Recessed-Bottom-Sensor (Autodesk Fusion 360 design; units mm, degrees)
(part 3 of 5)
sketch "Restore cam service opening after obsolete bore closure" plane through (23.9, 0, 0) normal (1, 0, 0) x axis (0, 0, -1)
  line L1 (-42.2047, 46.7373) -> (-43.8497, 47.5044)
  line L2 (-40.5875, 45.9133) -> (-42.2047, 46.7373)
  line L3 (-39, 45.0333) -> (-40.5875, 45.9133)
  line L4 (-37.4442, 44.0985) -> (-39, 45.0333)
  line L5 (-35.922, 43.11) -> (-37.4442, 44.0985)
  line L6 (-34.4352, 42.0689) -> (-35.922, 43.11)
  line L7 (-32.9856, 40.9766) -> (-34.4352, 42.0689)
  line L8 (-31.575, 39.8343) -> (-32.9856, 40.9766)
  line L9 (-30.2052, 38.6435) -> (-31.575, 39.8343)
  line L10 (-28.8778, 37.4057) -> (-30.2052, 38.6435)
  line L11 (-27.5943, 36.1222) -> (-28.8778, 37.4057)
  line L12 (-26.3565, 34.7948) -> (-27.5943, 36.1222)
  line L13 (-25.1657, 33.425) -> (-26.3565, 34.7948)
  line L14 (-24.0234, 32.0144) -> (-25.1657, 33.425)
  line L15 (-22.9311, 30.5648) -> (-24.0234, 32.0144)
  line L16 (-21.89, 29.078) -> (-22.9311, 30.5648)
  line L17 (-20.9015, 27.5558) -> (-21.89, 29.078)
  line L18 (-19.9667, 26) -> (-20.9015, 27.5558)
  line L19 (-19.0867, 24.4125) -> (-19.9667, 26)
  line L20 (-18.2627, 22.7953) -> (-19.0867, 24.4125)
  line L21 (-17.4956, 21.1503) -> (-18.2627, 22.7953)
  line L22 (-16.7864, 19.4795) -> (-17.4956, 21.1503)
  line L23 (-16.136, 17.785) -> (-16.7864, 19.4795)
  line L24 (-15.5451, 16.0689) -> (-16.136, 17.785)
  line L25 (-15.0144, 14.3331) -> (-15.5451, 16.0689)
  line L26 (-14.5446, 12.5799) -> (-15.0144, 14.3331)
  line L27 (-14.1363, 10.8114) -> (-14.5446, 12.5799)
  line L28 (-13.79, 9.0297) -> (-14.1363, 10.8114)
  line L29 (-13.5061, 7.237) -> (-13.79, 9.0297)
  line L30 (-13.2849, 5.4355) -> (-13.5061, 7.237)
  line L31 (-13.1267, 3.6273) -> (-13.2849, 5.4355)
  line L32 (-13.0317, 1.8148) -> (-13.1267, 3.6273)
  line L33 (-13, 0) -> (-13.0317, 1.8148)
  line L34 (-13.0317, -1.8148) -> (-13, 0)
  line L35 (-13.1267, -3.6273) -> (-13.0317, -1.8148)
  line L36 (-13.2849, -5.4355) -> (-13.1267, -3.6273)
  line L37 (-13.5061, -7.237) -> (-13.2849, -5.4355)
  line L38 (-13.79, -9.0297) -> (-13.5061, -7.237)
  line L39 (-14.1363, -10.8114) -> (-13.79, -9.0297)
  line L40 (-14.5446, -12.5799) -> (-14.1363, -10.8114)
  line L41 (-15.0144, -14.3331) -> (-14.5446, -12.5799)
  line L42 (-15.5451, -16.0689) -> (-15.0144, -14.3331)
  line L43 (-16.136, -17.785) -> (-15.5451, -16.0689)
  line L44 (-16.7864, -19.4795) -> (-16.136, -17.785)
  line L45 (-17.4956, -21.1503) -> (-16.7864, -19.4795)
  line L46 (-18.2627, -22.7953) -> (-17.4956, -21.1503)
  line L47 (-19.0867, -24.4125) -> (-18.2627, -22.7953)
  line L48 (-19.9667, -26) -> (-19.0867, -24.4125)
  line L49 (-20.9015, -27.5558) -> (-19.9667, -26)
  line L50 (-21.89, -29.078) -> (-20.9015, -27.5558)
  line L51 (-22.9311, -30.5648) -> (-21.89, -29.078)
  line L52 (-24.0234, -32.0144) -> (-22.9311, -30.5648)
  line L53 (-25.1657, -33.425) -> (-24.0234, -32.0144)
  line L54 (-26.3565, -34.7948) -> (-25.1657, -33.425)
  line L55 (-27.5943, -36.1222) -> (-26.3565, -34.7948)
  line L56 (-28.8778, -37.4057) -> (-27.5943, -36.1222)
  line L57 (-30.2052, -38.6435) -> (-28.8778, -37.4057)
  line L58 (-31.575, -39.8343) -> (-30.2052, -38.6435)
  line L59 (-32.9856, -40.9766) -> (-31.575, -39.8343)
  line L60 (-34.4352, -42.0689) -> (-32.9856, -40.9766)
  line L61 (-35.922, -43.11) -> (-34.4352, -42.0689)
  line L62 (-37.4442, -44.0985) -> (-35.922, -43.11)
  line L63 (-39, -45.0333) -> (-37.4442, -44.0985)
  line L64 (-40.5875, -45.9133) -> (-39, -45.0333)
  line L65 (-42.2047, -46.7373) -> (-40.5875, -45.9133)
  line L66 (-43.8497, -47.5044) -> (-42.2047, -46.7373)
  line L67 (-54.4248, -23.7522) -> (-43.8497, -47.5044)
  line L68 (-53.6024, -23.3686) -> (-54.4248, -23.7522)
  line L69 (-52.7937, -22.9566) -> (-53.6024, -23.3686)
  line L70 (-52, -22.5167) -> (-52.7937, -22.9566)
  line L71 (-51.2221, -22.0493) -> (-52, -22.5167)
  line L72 (-50.461, -21.555) -> (-51.2221, -22.0493)
  line L73 (-49.7176, -21.0344) -> (-50.461, -21.555)
  line L74 (-48.9928, -20.4883) -> (-49.7176, -21.0344)
  line L75 (-48.2875, -19.9172) -> (-48.9928, -20.4883)
  line L76 (-47.6026, -19.3218) -> (-48.2875, -19.9172)
  line L77 (-46.9389, -18.7028) -> (-47.6026, -19.3218)
  line L78 (-46.2972, -18.0611) -> (-46.9389, -18.7028)
  line L79 (-45.6782, -17.3974) -> (-46.2972, -18.0611)
  line L80 (-45.0828, -16.7125) -> (-45.6782, -17.3974)
  line L81 (-44.5117, -16.0072) -> (-45.0828, -16.7125)
  line L82 (-43.9656, -15.2824) -> (-44.5117, -16.0072)
  line L83 (-43.445, -14.539) -> (-43.9656, -15.2824)
  line L84 (-42.9507, -13.7779) -> (-43.445, -14.539)
  line L85 (-42.4833, -13) -> (-42.9507, -13.7779)
  line L86 (-42.0434, -12.2063) -> (-42.4833, -13)
  line L87 (-41.6314, -11.3976) -> (-42.0434, -12.2063)
  line L88 (-41.2478, -10.5752) -> (-41.6314, -11.3976)
  line L89 (-40.8932, -9.7398) -> (-41.2478, -10.5752)
  line L90 (-40.568, -8.8925) -> (-40.8932, -9.7398)
  line L91 (-40.2725, -8.0344) -> (-40.568, -8.8925)
  line L92 (-40.0072, -7.1666) -> (-40.2725, -8.0344)
  line L93 (-39.7723, -6.29) -> (-40.0072, -7.1666)
  line L94 (-39.5682, -5.4057) -> (-39.7723, -6.29)
  line L95 (-39.395, -4.5149) -> (-39.5682, -5.4057)
  line L96 (-39.253, -3.6185) -> (-39.395, -4.5149)
  line L97 (-39.1424, -2.7177) -> (-39.253, -3.6185)
  line L98 (-39.0633, -1.8137) -> (-39.1424, -2.7177)
  line L99 (-39.0158, -0.9074) -> (-39.0633, -1.8137)
  line L100 (-39, 0) -> (-39.0158, -0.9074)
  line L101 (-39.0158, 0.9074) -> (-39, 0)
  line L102 (-39.0633, 1.8137) -> (-39.0158, 0.9074)
  line L103 (-39.1424, 2.7177) -> (-39.0633, 1.8137)
  line L104 (-39.253, 3.6185) -> (-39.1424, 2.7177)
  line L105 (-39.395, 4.5149) -> (-39.253, 3.6185)
  line L106 (-39.5682, 5.4057) -> (-39.395, 4.5149)
  line L107 (-39.7723, 6.29) -> (-39.5682, 5.4057)
  line L108 (-40.0072, 7.1666) -> (-39.7723, 6.29)
  line L109 (-40.2725, 8.0344) -> (-40.0072, 7.1666)
  line L110 (-40.568, 8.8925) -> (-40.2725, 8.0344)
  line L111 (-40.8932, 9.7398) -> (-40.568, 8.8925)
  line L112 (-41.2478, 10.5752) -> (-40.8932, 9.7398)
  line L113 (-41.6314, 11.3976) -> (-41.2478, 10.5752)
  line L114 (-42.0434, 12.2063) -> (-41.6314, 11.3976)
  line L115 (-42.4833, 13) -> (-42.0434, 12.2063)
  line L116 (-42.9507, 13.7779) -> (-42.4833, 13)
  line L117 (-43.445, 14.539) -> (-42.9507, 13.7779)
  line L118 (-43.9656, 15.2824) -> (-43.445, 14.539)
  line L119 (-44.5117, 16.0072) -> (-43.9656, 15.2824)
  line L120 (-45.0828, 16.7125) -> (-44.5117, 16.0072)
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extrude "Extrude47" cut sketch "Restore cam service opening after obsolete bore closure" along normal blind 12.2
work_plane "WorkPlane48" AlongDistance -15.4 ExtraOffset 0
sketch "Fill former M5 stop nut pocket" plane through (-15.4, 0, 0) normal (1, 0, 0) x axis (0, 0, -1)
  circle C1 centre (-79.6754, -33.9652) radius 4.9
extrude "Extrude48" add sketch "Fill former M5 stop nut pocket" along normal blind 6.4
work_plane "WorkPlane49" AlongDistance -36 ExtraOffset 0
sketch "Fill former M5 stop bore" plane through (-36, 0, 0) normal (1, 0, 0) x axis (0, 0, -1)
  circle C1 centre (-79.6754, -33.9652) radius 2.71
extrude "Extrude49" add sketch "Fill former M5 stop bore" along normal blind 27
work_plane "WorkPlane50" AlongDistance -36.1 ExtraOffset 0
sketch "M3 stop reinforcement bore" plane through (-36.1, 0, 0) normal (1, 0, 0) x axis (0, 0, -1)
  circle C1 centre (-79.6754, -33.9652) radius 1.7
extrude "Extrude50" cut sketch "M3 stop reinforcement bore" along normal blind 27.2
work_plane "WorkPlane51" AlongDistance -13.5 ExtraOffset 0
sketch "Captive M3 locknut stop pocket" plane through (-13.5, 0, 0) normal (1, 0, 0) x axis (0, 0, -1)
  line L1 (-82.5754, -32.2908) -> (-79.6754, -30.6165)
  line L2 (-82.5754, -35.6395) -> (-82.5754, -32.2908)
  line L3 (-79.6754, -37.3138) -> (-82.5754, -35.6395)
  line L4 (-76.7754, -35.6395) -> (-79.6754, -37.3138)
  line L5 (-76.7754, -32.2908) -> (-76.7754, -35.6395)
  line L6 (-79.6754, -30.6165) -> (-76.7754, -32.2908)
extrude "Extrude51" cut sketch "Captive M3 locknut stop pocket" along normal blind 4.6
work_plane "WorkPlane52" AlongDistance -15.4 ExtraOffset 0
sketch "Fill former M5 stop nut pocket (1)" plane through (-15.4, 0, 0) normal (1, 0, 0) x axis (0, 0, -1)
  circle C1 centre (-79.6754, 33.9652) radius 4.9
extrude "Extrude52" add sketch "Fill former M5 stop nut pocket (1)" along normal blind 6.4
work_plane "WorkPlane53" AlongDistance -36 ExtraOffset 0
sketch "Fill former M5 stop bore (1)" plane through (-36, 0, 0) normal (1, 0, 0) x axis (0, 0, -1)
  circle C1 centre (-79.6754, 33.9652) radius 2.71
extrude "Extrude53" add sketch "Fill former M5 stop bore (1)" along normal blind 27
work_plane "WorkPlane54" AlongDistance -36.1 ExtraOffset 0
sketch "M3 stop reinforcement bore (1)" plane through (-36.1, 0, 0) normal (1, 0, 0) x axis (0, 0, -1)
  circle C1 centre (-79.6754, 33.9652) radius 1.7
extrude "Extrude54" cut sketch "M3 stop reinforcement bore (1)" along normal blind 27.2
work_plane "WorkPlane55" AlongDistance -13.5 ExtraOffset 0
sketch "Captive M3 locknut stop pocket (1)" plane through (-13.5, 0, 0) normal (1, 0, 0) x axis (0, 0, -1)
  line L1 (-82.5754, 35.6395) -> (-79.6754, 37.3138)
  line L2 (-82.5754, 32.2908) -> (-82.5754, 35.6395)
  line L3 (-79.6754, 30.6165) -> (-82.5754, 32.2908)
  line L4 (-76.7754, 32.2908) -> (-79.6754, 30.6165)
  line L5 (-76.7754, 35.6395) -> (-76.7754, 32.2908)
  line L6 (-79.6754, 37.3138) -> (-76.7754, 35.6395)
extrude "Extrude55" cut sketch "Captive M3 locknut stop pocket (1)" along normal blind 4.6
work_plane "WorkPlane56" AlongDistance -17.5 ExtraOffset 0
sketch "Recess M3 locknut to keep bolt inside stop" plane through (-17.5, 0, 0) normal (1, 0, 0) x axis (0, 0, -1)
  line L1 (-82.5754, -32.2908) -> (-79.6754, -30.6165)
  line L2 (-82.5754, -35.6395) -> (-82.5754, -32.2908)
  line L3 (-79.6754, -37.3138) -> (-82.5754, -35.6395)
  line L4 (-76.7754, -35.6395) -> (-79.6754, -37.3138)
  line L5 (-76.7754, -32.2908) -> (-76.7754, -35.6395)
  line L6 (-79.6754, -30.6165) -> (-76.7754, -32.2908)
extrude "Extrude56" cut sketch "Recess M3 locknut to keep bolt inside stop" along normal blind 4.01
work_plane "WorkPlane57" AlongDistance -17.5 ExtraOffset 0
sketch "Recess M3 locknut to keep bolt inside stop (1)" plane through (-17.5, 0, 0) normal (1, 0, 0) x axis (0, 0, -1)
  line L1 (-82.5754, 35.6395) -> (-79.6754, 37.3138)
  line L2 (-82.5754, 32.2908) -> (-82.5754, 35.6395)
  line L3 (-79.6754, 30.6165) -> (-82.5754, 32.2908)
  line L4 (-76.7754, 32.2908) -> (-79.6754, 30.6165)
  line L5 (-76.7754, 35.6395) -> (-76.7754, 32.2908)
  line L6 (-79.6754, 37.3138) -> (-76.7754, 35.6395)
extrude "Extrude57" cut sketch "Recess M3 locknut to keep bolt inside stop (1)" along normal blind 4.01
work_plane "WorkPlane6" AlongDistance -7.2 ExtraOffset 0
sketch "Upright socket roof 45 degrees" plane through (0, -7.2, 0) normal (0, 1, 0) x axis (1, 0, 0)
  line L1 (-7.2, -196) -> (0, -196)
  line L2 (0, -203.2) -> (-7.2, -196)
  line L3 (0, -196) -> (0, -203.2)
extrude "Extrude5" cut sketch "Upright socket roof 45 degrees" along normal blind 14.4
work_plane "WorkPlane8" AlongDistance -7.2 ExtraOffset 0
sketch "Upright socket roof 45 degrees" plane through (0, -7.2, 0) normal (0, 1, 0) x axis (1, 0, 0)
  line L1 (7.2, -196) -> (0, -196)
  line L2 (0, -203.2) -> (7.2, -196)
  line L3 (0, -196) -> (0, -203.2)
extrude "Extrude7" cut sketch "Upright socket roof 45 degrees" along normal blind 14.4
work_plane "WorkPlane58" AlongDistance -36 ExtraOffset 0
sketch "Stock M5x14 mounting seat Z64" plane through (-36, 0, 0) normal (1, 0, 0) x axis (0, 0, -1)
  line L1 (-63, -70) -> (-63, -95)
  line L2 (-64, -70) -> (-63, -70)
  line L3 (-64, -95) -> (-64, -70)
  line L4 (-63, -95) -> (-64, -95)
extrude "Extrude58" add sketch "Stock M5x14 mounting seat Z64" along normal blind 12
work_plane "WorkPlane59" AlongDistance 62.9 ExtraOffset 0
sketch "Continue rail clearance through new seat" plane through (0, 0, 62.9) normal (0, 0, 1) x axis (1, 0, 0)
  circle C1 centre (-30, -85) radius 2.7
extrude "Extrude59" cut sketch "Continue rail clearance through new seat" along normal blind 1.2
work_plane "WorkPlane60" AlongDistance -36 ExtraOffset 0
sketch "Stock M5x14 mounting seat Z64 (1)" plane through (-36, 0, 0) normal (1, 0, 0) x axis (0, 0, -1)
  line L1 (-63, 95) -> (-63, 70)
  line L2 (-64, 95) -> (-63, 95)
  line L3 (-64, 70) -> (-64, 95)
  line L4 (-63, 70) -> (-64, 70)
extrude "Extrude60" add sketch "Stock M5x14 mounting seat Z64 (1)" along normal blind 12
work_plane "WorkPlane61" AlongDistance 62.9 ExtraOffset 0
sketch "Continue rail clearance through new seat (1)" plane through (0, 0, 62.9) normal (0, 0, 1) x axis (1, 0, 0)
  circle C1 centre (-30, 85) radius 2.7
extrude "Extrude61" cut sketch "Continue rail clearance through new seat (1)" along normal blind 1.2
work_plane "WorkPlane62" AlongDistance -36 ExtraOffset 0
sketch "Close obsolete long pivot screw hole" plane through (-36, 0, 0) normal (1, 0, 0) x axis (0, 0, -1)
  circle C1 centre (-12, -35) radius 1.71
extrude "Extrude62" add sketch "Close obsolete long pivot screw hole" along normal blind 12
work_plane "WorkPlane63" AlongDistance -26 ExtraOffset 0
sketch "Blind captive printed pivot seat" plane through (-26, 0, 0) normal (1, 0, 0) x axis (0, 0, -1)
  circle C1 centre (-12, -35) radius 4.15
extrude "Extrude63" cut sketch "Blind captive printed pivot seat" along normal blind 2.1
work_plane "WorkPlane48" AlongDistance 24 ExtraOffset 0
sketch "Stock M5x14 mounting seat Z64" plane through (24, 0, 0) normal (1, 0, 0) x axis (0, 0, -1)
  line L1 (-63, -70) -> (-63, -95)
  line L2 (-64, -70) -> (-63, -70)
  line L3 (-64, -95) -> (-64, -70)
  line L4 (-63, -95) -> (-64, -95)
extrude "Extrude48" add sketch "Stock M5x14 mounting seat Z64" along normal blind 12
work_plane "WorkPlane49" AlongDistance 62.9 ExtraOffset 0
sketch "Continue rail clearance through new seat" plane through (0, 0, 62.9) normal (0, 0, 1) x axis (1, 0, 0)
  circle C1 centre (30, -85) radius 2.7
extrude "Extrude49" cut sketch "Continue rail clearance through new seat" along normal blind 1.2
work_plane "WorkPlane50" AlongDistance 24 ExtraOffset 0
sketch "Stock M5x14 mounting seat Z64 (1)" plane through (24, 0, 0) normal (1, 0, 0) x axis (0, 0, -1)
  line L1 (-63, 95) -> (-63, 70)
  line L2 (-64, 95) -> (-63, 95)
  line L3 (-64, 70) -> (-64, 95)
  line L4 (-63, 70) -> (-64, 70)
extrude "Extrude50" add sketch "Stock M5x14 mounting seat Z64 (1)" along normal blind 12
work_plane "WorkPlane51" AlongDistance 62.9 ExtraOffset 0
sketch "Continue rail clearance through new seat (1)" plane through (0, 0, 62.9) normal (0, 0, 1) x axis (1, 0, 0)
  circle C1 centre (30, 85) radius 2.7
extrude "Extrude51" cut sketch "Continue rail clearance through new seat (1)" along normal blind 1.2
work_plane "WorkPlane52" AlongDistance 24 ExtraOffset 0
sketch "Close obsolete long pivot screw hole" plane through (24, 0, 0) normal (1, 0, 0) x axis (0, 0, -1)
  circle C1 centre (-12, -35) radius 1.71
extrude "Extrude52" add sketch "Close obsolete long pivot screw hole" along normal blind 12
work_plane "WorkPlane53" AlongDistance 23.9 ExtraOffset 0
sketch "Blind captive printed pivot seat" plane through (23.9, 0, 0) normal (1, 0, 0) x axis (0, 0, -1)
  circle C1 centre (-12, -35) radius 4.15
extrude "Extrude53" cut sketch "Blind captive printed pivot seat" along normal blind 2.1
work_plane "WorkPlane1" AlongDistance -25.85 ExtraOffset 0
sketch "Captured axle 0.3 mm total end clearance" plane through (-25.85, 0, 0) normal (1, 0, 0) x axis (0, 0, -1)
  circle C1 centre (-12, -35) radius 4
extrude "Extrude1" new body sketch "Captured axle 0.3 mm total end clearance" along normal blind 51.7 bodies "P25 Captured printed pivot lower half"
work_plane "WorkPlane2" AlongDistance -26 ExtraOffset 0
sketch "Longitudinal flat print face" plane through (-26, 0, 0) normal (1, 0, 0) x axis (0, 0, -1)
  line L1 (-7, -30) -> (-7, -35)
  line L2 (-17, -30) -> (-7, -30)
  line L3 (-17, -35) -> (-17, -30)
  line L4 (-7, -35) -> (-17, -35)
extrude "Extrude2" cut sketch "Longitudinal flat print face" along normal blind 52
work_plane "WorkPlane1" AlongDistance -25.85 ExtraOffset 0
sketch "Captured axle 0.3 mm total end clearance" plane through (-25.85, 0, 0) normal (1, 0, 0) x axis (0, 0, -1)
  circle C1 centre (-12, -35) radius 4
extrude "Extrude1" new body sketch "Captured axle 0.3 mm total end clearance" along normal blind 51.7 bodies "P26 Captured printed pivot upper half"
work_plane "WorkPlane2" AlongDistance -26 ExtraOffset 0
sketch "Longitudinal flat print face" plane through (-26, 0, 0) normal (1, 0, 0) x axis (0, 0, -1)
  line L1 (-7, -35) -> (-7, -40)
  line L2 (-17, -35) -> (-7, -35)
  line L3 (-17, -40) -> (-17, -35)
  line L4 (-7, -40) -> (-17, -40)
extrude "Extrude2" cut sketch "Longitudinal flat print face" along normal blind 52
work_plane "WorkPlane9" AlongDistance 9 ExtraOffset 0
sketch "Recess for stocked M3x20 grip screw" plane through (9, 0, 0) normal (1, 0, 0) x axis (0, 0, -1)
  circle C1 centre (-180, 0) radius 3.1
extrude "Extrude8" cut sketch "Recess for stocked M3x20 grip screw" along normal blind 3.6
work_plane "WorkPlane1" AlongDistance -11 ExtraOffset 0
sketch "Grip M3x20 cap head 180" plane through (-11, 0, 0) normal (1, 0, 0) x axis (0, 0, -1)
  circle C1 centre (-180, 0) radius 1.5
extrude "Extrude1" new body sketch "Grip M3x20 cap head 180" along normal blind 20 bodies "HARDWARE Grip M3x20 cap head 180"
work_plane "WorkPlane2" AlongDistance 9 ExtraOffset 0
sketch "Button head" plane through (9, 0, 0) normal (1, 0, 0) x axis (0, 0, -1)
  circle C1 centre (-180, 0) radius 2.75
extrude "Extrude2" add sketch "Button head" along normal blind 3
work_plane "WorkPlane10" AlongDistance 9 ExtraOffset 0
sketch "Recess for stocked M3x20 grip screw (1)" plane through (9, 0, 0) normal (1, 0, 0) x axis (0, 0, -1)
  circle C1 centre (-190, 0) radius 3.1
extrude "Extrude9" cut sketch "Recess for stocked M3x20 grip screw (1)" along normal blind 3.6
work_plane "WorkPlane1" AlongDistance -11 ExtraOffset 0
sketch "Grip M3x20 cap head 190" plane through (-11, 0, 0) normal (1, 0, 0) x axis (0, 0, -1)
  circle C1 centre (-190, 0) radius 1.5
extrude "Extrude1" new body sketch "Grip M3x20 cap head 190" along normal blind 20 bodies "HARDWARE Grip M3x20 cap head 190"
work_plane "WorkPlane2" AlongDistance 9 ExtraOffset 0
sketch "Button head" plane through (9, 0, 0) normal (1, 0, 0) x axis (0, 0, -1)
  circle C1 centre (-190, 0) radius 2.75
extrude "Extrude2" add sketch "Button head" along normal blind 3
work_plane "WorkPlane64" AlongDistance -36.1 ExtraOffset 0
sketch "Stock M3x20 stop recessed cap head" plane through (-36.1, 0, 0) normal (1, 0, 0) x axis (0, 0, -1)
  circle C1 centre (-79.6754, -33.9652) radius 3.1
extrude "Extrude64" cut sketch "Stock M3x20 stop recessed cap head" along normal blind 4.6
work_plane "WorkPlane1" AlongDistance -31.5 ExtraOffset 0
sketch "Stop M3x20 cap head -1" plane through (-31.5, 0, 0) normal (1, 0, 0) x axis (0, 0, -1)
  circle C1 centre (-79.6754, -33.9652) radius 1.5
extrude "Extrude1" new body sketch "Stop M3x20 cap head -1" along normal blind 20 bodies "HARDWARE Stop M3x20 cap head -1"
work_plane "WorkPlane2" AlongDistance -34.5 ExtraOffset 0
sketch "Button head" plane through (-34.5, 0, 0) normal (1, 0, 0) x axis (0, 0, -1)
  circle C1 centre (-79.6754, -33.9652) radius 2.75
extrude "Extrude2" add sketch "Button head" along normal blind 3
work_plane "WorkPlane1" AlongDistance -17.5 ExtraOffset 0
sketch "Stop M3 plain captive nut -1" plane through (-17.5, 0, 0) normal (1, 0, 0) x axis (0, 0, -1)
  line L1 (-82.4254, -32.3774) -> (-79.6754, -30.7897)
  line L2 (-82.4254, -35.5529) -> (-82.4254, -32.3774)
  line L3 (-79.6754, -37.1406) -> (-82.4254, -35.5529)
  line L4 (-76.9254, -35.5529) -> (-79.6754, -37.1406)
  line L5 (-76.9254, -32.3774) -> (-76.9254, -35.5529)
  line L6 (-79.6754, -30.7897) -> (-76.9254, -32.3774)
extrude "Extrude1" new body sketch "Stop M3 plain captive nut -1" along normal blind 2.4 bodies "HARDWARE Stop M3 plain captive nut -1"
work_plane "WorkPlane2" AlongDistance -17.6 ExtraOffset 0
sketch "Thread envelope" plane through (-17.6, 0, 0) normal (1, 0, 0) x axis (0, 0, -1)
  circle C1 centre (-79.6754, -33.9652) radius 1.5
extrude "Extrude2" cut sketch "Thread envelope" along normal blind 2.6
work_plane "WorkPlane65" AlongDistance -36.1 ExtraOffset 0
sketch "Stock M3x20 stop recessed cap head (1)" plane through (-36.1, 0, 0) normal (1, 0, 0) x axis (0, 0, -1)
  circle C1 centre (-79.6754, 33.9652) radius 3.1
extrude "Extrude65" cut sketch "Stock M3x20 stop recessed cap head (1)" along normal blind 4.6
work_plane "WorkPlane1" AlongDistance -31.5 ExtraOffset 0
sketch "Stop M3x20 cap head 1" plane through (-31.5, 0, 0) normal (1, 0, 0) x axis (0, 0, -1)
  circle C1 centre (-79.6754, 33.9652) radius 1.5
extrude "Extrude1" new body sketch "Stop M3x20 cap head 1" along normal blind 20 bodies "HARDWARE Stop M3x20 cap head 1"
work_plane "WorkPlane2" AlongDistance -34.5 ExtraOffset 0
sketch "Button head" plane through (-34.5, 0, 0) normal (1, 0, 0) x axis (0, 0, -1)
  circle C1 centre (-79.6754, 33.9652) radius 2.75
extrude "Extrude2" add sketch "Button head" along normal blind 3
work_plane "WorkPlane1" AlongDistance -17.5 ExtraOffset 0
sketch "Stop M3 plain captive nut 1" plane through (-17.5, 0, 0) normal (1, 0, 0) x axis (0, 0, -1)
  line L1 (-82.4254, 35.5529) -> (-79.6754, 37.1406)
  line L2 (-82.4254, 32.3774) -> (-82.4254, 35.5529)
  line L3 (-79.6754, 30.7897) -> (-82.4254, 32.3774)
  line L4 (-76.9254, 32.3774) -> (-79.6754, 30.7897)
  line L5 (-76.9254, 35.5529) -> (-76.9254, 32.3774)
  line L6 (-79.6754, 37.1406) -> (-76.9254, 35.5529)
extrude "Extrude1" new body sketch "Stop M3 plain captive nut 1" along normal blind 2.4 bodies "HARDWARE Stop M3 plain captive nut 1"
work_plane "WorkPlane2" AlongDistance -17.6 ExtraOffset 0
sketch "Thread envelope" plane through (-17.6, 0, 0) normal (1, 0, 0) x axis (0, 0, -1)
  circle C1 centre (-79.6754, 33.9652) radius 1.5
extrude "Extrude2" cut sketch "Thread envelope" along normal blind 2.6
work_plane "WorkPlane10" AlongDistance 7 ExtraOffset 0
sketch "Bearing inner race support pad" plane through (7, 0, 0) normal (1, 0, 0) x axis (0, 0, -1)
  circle C1 centre (-12, 0) radius 2.4
extrude "Extrude10" add sketch "Bearing inner race support pad" along normal blind 1
work_plane "WorkPlane11" AlongDistance 6.9 ExtraOffset 0
sketch "Preserve roller screw clearance" plane through (6.9, 0, 0) normal (1, 0, 0) x axis (0, 0, -1)
  circle C1 centre (-12, 0) radius 1.7
extrude "Extrude11" cut sketch "Preserve roller screw clearance" along normal blind 1.2
work_plane "WorkPlane12" AlongDistance 16 ExtraOffset 0
sketch "Bearing inner race support pad (1)" plane through (16, 0, 0) normal (1, 0, 0) x axis (0, 0, -1)
  circle C1 centre (-12, 0) radius 2.4
extrude "Extrude12" add sketch "Bearing inner race support pad (1)" along normal blind 1
work_plane "WorkPlane13" AlongDistance 15.9 ExtraOffset 0
sketch "Preserve roller screw clearance (1)" plane through (15.9, 0, 0) normal (1, 0, 0) x axis (0, 0, -1)
  circle C1 centre (-12, 0) radius 1.7
extrude "Extrude13" cut sketch "Preserve roller screw clearance (1)" along normal blind 1.2
work_plane "WorkPlane1" AlongDistance 8 ExtraOffset 0
sketch "Stock 623ZZ envelope 3x10x4" plane through (8, 0, 0) normal (1, 0, 0) x axis (0, 0, -1)
  circle C1 centre (-12, 0) radius 5
extrude "Extrude1" new body sketch "Stock 623ZZ envelope 3x10x4" along normal blind 4 bodies "HARDWARE 623ZZ roller bearing at 8"
work_plane "WorkPlane2" AlongDistance 7.9 ExtraOffset 0
sketch "Bearing inner race bore" plane through (7.9, 0, 0) normal (1, 0, 0) x axis (0, 0, -1)
  circle C1 centre (-12, 0) radius 1.5
extrude "Extrude2" cut sketch "Bearing inner race bore" along normal blind 4.2
work_plane "WorkPlane1" AlongDistance 12 ExtraOffset 0
sketch "Stock 623ZZ envelope 3x10x4" plane through (12, 0, 0) normal (1, 0, 0) x axis (0, 0, -1)
  circle C1 centre (-12, 0) radius 5
extrude "Extrude1" new body sketch "Stock 623ZZ envelope 3x10x4" along normal blind 4 bodies "HARDWARE 623ZZ roller bearing at 12"
work_plane "WorkPlane2" AlongDistance 11.9 ExtraOffset 0
sketch "Bearing inner race bore" plane through (11.9, 0, 0) normal (1, 0, 0) x axis (0, 0, -1)
  circle C1 centre (-12, 0) radius 1.5
extrude "Extrude2" cut sketch "Bearing inner race bore" along normal blind 4.2
work_plane "WorkPlane45" AlongDistance 38 ExtraOffset 0
sketch "Close former long guide bore" plane through (0, 0, 38) normal (0, 0, 1) x axis (1, 0, 0)
  circle C1 centre (5, -55) radius 1.71
extrude "Extrude45" add sketch "Close former long guide bore" along normal blind 21
work_plane "WorkPlane46" AlongDistance 38 ExtraOffset 0
sketch "Close former long guide bore (1)" plane through (0, 0, 38) normal (0, 0, 1) x axis (1, 0, 0)
  circle C1 centre (19, -55) radius 1.71
extrude "Extrude46" add sketch "Close former long guide bore (1)" along normal blind 21
work_plane "WorkPlane47" AlongDistance 38 ExtraOffset 0
sketch "Close obsolete M4 nut pocket" plane through (0, 0, 38) normal (0, 0, 1) x axis (1, 0, 0)
  line L1 (14.1362, -51.3) -> (16.2724, -55)
  line L2 (9.8638, -51.3) -> (14.1362, -51.3)
  line L3 (7.7276, -55) -> (9.8638, -51.3)
  line L4 (9.8638, -58.7) -> (7.7276, -55)
  line L5 (14.1362, -58.7) -> (9.8638, -58.7)
  line L6 (16.2724, -55) -> (14.1362, -58.7)
extrude "Extrude47" add sketch "Close obsolete M4 nut pocket" along normal blind 3.5
work_plane "WorkPlane48" AlongDistance 38 ExtraOffset 0
sketch "Close obsolete M4 adjuster passage" plane through (0, 0, 38) normal (0, 0, 1) x axis (1, 0, 0)
  circle C1 centre (12, -55) radius 2.21
extrude "Extrude48" add sketch "Close obsolete M4 adjuster passage" along normal blind 21
work_plane "WorkPlane49" AlongDistance 37.9 ExtraOffset 0
sketch "M3 preload adjuster passage" plane through (0, 0, 37.9) normal (0, 0, 1) x axis (1, 0, 0)
  circle C1 centre (12, -55) radius 1.7
extrude "Extrude49" cut sketch "M3 preload adjuster passage" along normal blind 21.2
work_plane "WorkPlane50" AlongDistance 37.9 ExtraOffset 0
sketch "M3 preload insert from spring side" plane through (0, 0, 37.9) normal (0, 0, 1) x axis (1, 0, 0)
  circle C1 centre (12, -55) radius 2
extrude "Extrude50" cut sketch "M3 preload insert from spring side" along normal blind 6.9
work_plane "WorkPlane51" AlongDistance 55 ExtraOffset 0
sketch "Recessed preload head and limiter access" plane through (0, 0, 55) normal (0, 0, 1) x axis (1, 0, 0)
  circle C1 centre (12, -55) radius 3.4
extrude "Extrude51" cut sketch "Recessed preload head and limiter access" along normal blind 4.1
work_plane "WorkPlane52" AlongDistance 37.9 ExtraOffset 0
sketch "Short guide M3 insert from underside" plane through (0, 0, 37.9) normal (0, 0, 1) x axis (1, 0, 0)
  circle C1 centre (4, -55) radius 2
extrude "Extrude52" cut sketch "Short guide M3 insert from underside" along normal blind 6.9
work_plane "WorkPlane1" AlongDistance 32 ExtraOffset 0
sketch "Short compression sleeve" plane through (0, 0, 32) normal (0, 0, 1) x axis (1, 0, 0)
  circle C1 centre (4, -55) radius 2.5
extrude "Extrude1" new body sketch "Short compression sleeve" along normal blind 6 bodies "P27 Printed guide sleeve 4"
work_plane "WorkPlane2" AlongDistance 31.9 ExtraOffset 0
sketch "Guide screw bore" plane through (0, 0, 31.9) normal (0, 0, 1) x axis (1, 0, 0)
  circle C1 centre (4, -55) radius 1.65
extrude "Extrude2" cut sketch "Guide screw bore" along normal blind 6.2
work_plane "WorkPlane1" AlongDistance 32 ExtraOffset 0
sketch "Cup guide M3x12 4" plane through (0, 0, 32) normal (0, 0, 1) x axis (1, 0, 0)
  circle C1 centre (4, -55) radius 1.5
extrude "Extrude1" new body sketch "Cup guide M3x12 4" along normal blind 12 bodies "HARDWARE Cup guide M3x12 4"
work_plane "WorkPlane2" AlongDistance 29 ExtraOffset 0
sketch "Button head" plane through (0, 0, 29) normal (0, 0, 1) x axis (1, 0, 0)
  circle C1 centre (4, -55) radius 2.75
extrude "Extrude2" add sketch "Button head" along normal blind 3
work_plane "WorkPlane53" AlongDistance 37.9 ExtraOffset 0
sketch "Short guide M3 insert from underside (1)" plane through (0, 0, 37.9) normal (0, 0, 1) x axis (1, 0, 0)
  circle C1 centre (20, -55) radius 2
extrude "Extrude53" cut sketch "Short guide M3 insert from underside (1)" along normal blind 6.9
work_plane "WorkPlane1" AlongDistance 32 ExtraOffset 0
sketch "Short compression sleeve" plane through (0, 0, 32) normal (0, 0, 1) x axis (1, 0, 0)
  circle C1 centre (20, -55) radius 2.5
extrude "Extrude1" new body sketch "Short compression sleeve" along normal blind 6 bodies "P27 Printed guide sleeve 20"
work_plane "WorkPlane2" AlongDistance 31.9 ExtraOffset 0
sketch "Guide screw bore" plane through (0, 0, 31.9) normal (0, 0, 1) x axis (1, 0, 0)
  circle C1 centre (20, -55) radius 1.65
extrude "Extrude2" cut sketch "Guide screw bore" along normal blind 6.2
work_plane "WorkPlane1" AlongDistance 32 ExtraOffset 0
sketch "Cup guide M3x12 20" plane through (0, 0, 32) normal (0, 0, 1) x axis (1, 0, 0)
  circle C1 centre (20, -55) radius 1.5
extrude "Extrude1" new body sketch "Cup guide M3x12 20" along normal blind 12 bodies "HARDWARE Cup guide M3x12 20"
work_plane "WorkPlane2" AlongDistance 29 ExtraOffset 0
sketch "Button head" plane through (0, 0, 29) normal (0, 0, 1) x axis (1, 0, 0)
  circle C1 centre (20, -55) radius 2.75
extrude "Extrude2" add sketch "Button head" along normal blind 3
work_plane "WorkPlane1" AlongDistance 0.2 ExtraOffset 0
sketch "Wide stock spring seat" plane through (0.2, 0, 0) normal (1, 0, 0) x axis (0, 0, -1)
  line L1 (-35, -49) -> (-35, -61)
  line L2 (-37, -49) -> (-35, -49)
  line L3 (-37, -61) -> (-37, -49)
  line L4 (-35, -61) -> (-37, -61)
extrude "Extrude1" new body sketch "Wide stock spring seat" along normal blind 23.6 bodies "P14 Captive spring cup for 9 mm spring"
work_plane "WorkPlane2" AlongDistance 29 ExtraOffset 0
sketch "Provisional 6 mm spring pilot" plane through (0, 0, 29) normal (0, 0, 1) x axis (1, 0, 0)
  circle C1 centre (12, -55) radius 3
extrude "Extrude2" add sketch "Provisional 6 mm spring pilot" along normal blind 6
work_plane "WorkPlane3" AlongDistance 34.9 ExtraOffset 0
sketch "Printed guide running clearance" plane through (0, 0, 34.9) normal (0, 0, 1) x axis (1, 0, 0)
  circle C1 centre (4, -55) radius 2.7
extrude "Extrude3" cut sketch "Printed guide running clearance" along normal blind 2.2
work_plane "WorkPlane4" AlongDistance 34.9 ExtraOffset 0
sketch "Printed guide running clearance (1)" plane through (0, 0, 34.9) normal (0, 0, 1) x axis (1, 0, 0)
  circle C1 centre (20, -55) radius 2.7
extrude "Extrude4" cut sketch "Printed guide running clearance (1)" along normal blind 2.2
work_plane "WorkPlane1" AlongDistance 55 ExtraOffset 0
sketch "Preserve one mm additional compression limit" plane through (0, 0, 55) normal (0, 0, 1) x axis (1, 0, 0)
  circle C1 centre (12, -55) radius 3.2
extrude "Extrude1" new body sketch "Preserve one mm additional compression limit" along normal blind 2 bodies "P15 Recessed preload limit collar 1 mm"
work_plane "WorkPlane2" AlongDistance 54.9 ExtraOffset 0
sketch "M3 adjuster clearance" plane through (0, 0, 54.9) normal (0, 0, 1) x axis (1, 0, 0)
  circle C1 centre (12, -55) radius 1.7
extrude "Extrude2" cut sketch "M3 adjuster clearance" along normal blind 2.2
work_plane "WorkPlane1" AlongDistance 37 ExtraOffset 0
sketch "Preload M3x20 cap head" plane through (0, 0, 37) normal (0, 0, 1) x axis (1, 0, 0)
  circle C1 centre (12, -55) radius 1.5
extrude "Extrude1" new body sketch "Preload M3x20 cap head" along normal blind 20 bodies "HARDWARE Preload M3x20 cap head"
work_plane "WorkPlane2" AlongDistance 57 ExtraOffset 0
sketch "Button head" plane through (0, 0, 57) normal (0, 0, 1) x axis (1, 0, 0)
  circle C1 centre (12, -55) radius 2.75
extrude "Extrude2" add sketch "Button head" along normal blind 3
work_plane "WorkPlane1" AlongDistance 18 ExtraOffset 0
sketch "Provisional stock spring installed envelope" plane through (0, 0, 18) normal (0, 0, 1) x axis (1, 0, 0)
  circle C1 centre (12, -55) radius 4.5
extrude "Extrude1" new body sketch "Provisional stock spring installed envelope" along normal blind 17 bodies "REFERENCE Stock spring OD9 wire1 free20 - rate and solid height assumed"
work_plane "WorkPlane2" AlongDistance 17.9 ExtraOffset 0
sketch "Stock spring nominal ID7" plane through (0, 0, 17.9) normal (0, 0, 1) x axis (1, 0, 0)
  circle C1 centre (12, -55) radius 3.5
extrude "Extrude2" cut sketch "Stock spring nominal ID7" along normal blind 17.2
work_plane "WorkPlane54" AlongDistance 36 ExtraOffset 0
sketch "Remove long sensor carriage supports" plane through (36, 0, 0) normal (1, 0, 0) x axis (0, 0, -1)
  line L1 (-46, 34) -> (-46, -34)
  line L2 (-84, 34) -> (-46, 34)
  line L3 (-84, -34) -> (-84, 34)
  line L4 (-46, -34) -> (-84, -34)
extrude "Extrude54" cut sketch "Remove long sensor carriage supports" along normal blind 44.1
work_plane "WorkPlane55" AlongDistance 36 ExtraOffset 0
sketch "Compact sensor support" plane through (36, 0, 0) normal (1, 0, 0) x axis (0, 0, -1)
  line L1 (-49, -18) -> (-49, -28)
  line L2 (-81, -18) -> (-49, -18)
  line L3 (-81, -28) -> (-81, -18)
  line L4 (-49, -28) -> (-81, -28)
extrude "Extrude55" add sketch "Compact sensor support" along normal blind 30.15
work_plane "WorkPlane56" AlongDistance -28.1 ExtraOffset 0
sketch "Compact carriage M3 insert" plane through (0, -28.1, 0) normal (0, 1, 0) x axis (1, 0, 0)
  circle C1 centre (60.15, -65) radius 2
extrude "Extrude56" cut sketch "Compact carriage M3 insert" along normal blind 6.8
work_plane "WorkPlane57" AlongDistance 36 ExtraOffset 0
sketch "Compact sensor support (1)" plane through (36, 0, 0) normal (1, 0, 0) x axis (0, 0, -1)
  line L1 (-49, 28) -> (-49, 18)
  line L2 (-81, 28) -> (-49, 28)
  line L3 (-81, 18) -> (-81, 28)
  line L4 (-49, 18) -> (-81, 18)
extrude "Extrude57" add sketch "Compact sensor support (1)" along normal blind 30.15
work_plane "WorkPlane58" AlongDistance 21.3 ExtraOffset 0
sketch "Compact carriage M3 insert (1)" plane through (0, 21.3, 0) normal (0, 1, 0) x axis (1, 0, 0)
  circle C1 centre (60.15, -65) radius 2
extrude "Extrude58" cut sketch "Compact carriage M3 insert (1)" along normal blind 6.8
work_plane "WorkPlane59" AlongDistance 36 ExtraOffset 0
sketch "Restore cam service path beneath compact rails" plane through (36, 0, 0) normal (1, 0, 0) x axis (0, 0, -1)
  line L1 (-48.9, -18) -> (-48.9, -28)
  line L2 (-56, -18) -> (-48.9, -18)
  line L3 (-56, -28) -> (-56, -18)
  line L4 (-48.9, -28) -> (-56, -28)
extrude "Extrude59" cut sketch "Restore cam service path beneath compact rails" along normal blind 30.25
work_plane "WorkPlane60" AlongDistance 36 ExtraOffset 0
sketch "Restore cam service path beneath compact rails (1)" plane through (36, 0, 0) normal (1, 0, 0) x axis (0, 0, -1)
  line L1 (-48.9, 28) -> (-48.9, 18)
  line L2 (-56, 28) -> (-48.9, 28)
  line L3 (-56, 18) -> (-56, 28)
  line L4 (-48.9, 18) -> (-56, 18)
extrude "Extrude60" cut sketch "Restore cam service path beneath compact rails (1)" along normal blind 30.25
work_plane "WorkPlane66" AlongDistance 54.9 ExtraOffset 0
sketch "Support-free horizontal rail hole roof" plane through (0, 0, 54.9) normal (0, 0, 1) x axis (1, 0, 0)
  line L1 (-28.0908, -83.0908) -> (-28.0908, -86.9092)
  line L2 (-26.1816, -85) -> (-28.0908, -83.0908)
  line L3 (-28.0908, -86.9092) -> (-26.1816, -85)
extrude "Extrude66" cut sketch "Support-free horizontal rail hole roof" along normal blind 9.2
work_plane "WorkPlane67" AlongDistance 54.9 ExtraOffset 0
sketch "Support-free horizontal rail hole roof (1)" plane through (0, 0, 54.9) normal (0, 0, 1) x axis (1, 0, 0)
  line L1 (-28.0908, 86.9092) -> (-28.0908, 83.0908)
  line L2 (-26.1816, 85) -> (-28.0908, 86.9092)
  line L3 (-28.0908, 83.0908) -> (-26.1816, 85)
extrude "Extrude67" cut sketch "Support-free horizontal rail hole roof (1)" along normal blind 9.2
work_plane "WorkPlane61" AlongDistance 54.9 ExtraOffset 0
sketch "Support-free horizontal rail hole roof" plane through (0, 0, 54.9) normal (0, 0, 1) x axis (1, 0, 0)
  line L1 (31.9092, -83.0908) -> (31.9092, -86.9092)
  line L2 (33.8184, -85) -> (31.9092, -83.0908)
  line L3 (31.9092, -86.9092) -> (33.8184, -85)
extrude "Extrude61" cut sketch "Support-free horizontal rail hole roof" along normal blind 9.2
work_plane "WorkPlane62" AlongDistance 54.9 ExtraOffset 0
sketch "Support-free horizontal rail hole roof (1)" plane through (0, 0, 54.9) normal (0, 0, 1) x axis (1, 0, 0)
  line L1 (31.9092, 86.9092) -> (31.9092, 83.0908)
  line L2 (33.8184, 85) -> (31.9092, 86.9092)
  line L3 (31.9092, 83.0908) -> (33.8184, 85)
extrude "Extrude62" cut sketch "Support-free horizontal rail hole roof (1)" along normal blind 9.2
work_plane "WorkPlane14" AlongDistance 4 ExtraOffset 0
sketch "Reinforced roof over support-free pivot bore" plane through (4, 0, 0) normal (1, 0, 0) x axis (0, 0, -1)
  line L1 (-17.9, -29) -> (-17.9, -41)
  line L2 (-20, -29) -> (-17.9, -29)
  line L3 (-20, -41) -> (-20, -29)
  line L4 (-17.9, -41) -> (-20, -41)
extrude "Extrude14" add sketch "Reinforced roof over support-free pivot bore" along normal blind 3
work_plane "WorkPlane15" AlongDistance 4 ExtraOffset 0
sketch "Flat print foot below roller cheek" plane through (4, 0, 0) normal (1, 0, 0) x axis (0, 0, -1)
  line L1 (-6, 6) -> (-6, -6)
  line L2 (-12, 6) -> (-6, 6)
  line L3 (-12, -6) -> (-12, 6)
  line L4 (-6, -6) -> (-12, -6)
extrude "Extrude15" add sketch "Flat print foot below roller cheek" along normal blind 3
work_plane "WorkPlane16" AlongDistance 17 ExtraOffset 0
sketch "Reinforced roof over support-free pivot bore (1)" plane through (17, 0, 0) normal (1, 0, 0) x axis (0, 0, -1)
  line L1 (-17.9, -29) -> (-17.9, -41)
  line L2 (-20, -29) -> (-17.9, -29)
  line L3 (-20, -41) -> (-20, -29)
  line L4 (-17.9, -41) -> (-20, -41)
extrude "Extrude16" add sketch "Reinforced roof over support-free pivot bore (1)" along normal blind 3
work_plane "WorkPlane17" AlongDistance 17 ExtraOffset 0
sketch "Flat print foot below roller cheek (1)" plane through (17, 0, 0) normal (1, 0, 0) x axis (0, 0, -1)
  line L1 (-6, 6) -> (-6, -6)
  line L2 (-12, 6) -> (-6, 6)
  line L3 (-12, -6) -> (-12, 6)
  line L4 (-6, -6) -> (-12, -6)
extrude "Extrude17" add sketch "Flat print foot below roller cheek (1)" along normal blind 3
work_plane "WorkPlane18" AlongDistance 3.9 ExtraOffset 0
sketch "Follower horizontal bore 45 degree roof" plane through (3.9, 0, 0) normal (1, 0, 0) x axis (0, 0, -1)
  line L1 (-14.9345, -32.0655) -> (-14.9345, -37.9345)
  line L2 (-17.869, -35) -> (-14.9345, -32.0655)
  line L3 (-14.9345, -37.9345) -> (-17.869, -35)
extrude "Extrude18" cut sketch "Follower horizontal bore 45 degree roof" along normal blind 16.2
work_plane "WorkPlane19" AlongDistance 3.9 ExtraOffset 0
sketch "Follower horizontal bore 45 degree roof (1)" plane through (3.9, 0, 0) normal (1, 0, 0) x axis (0, 0, -1)
  line L1 (-13.2021, 1.2021) -> (-13.2021, -1.2021)
  line L2 (-14.4042, 0) -> (-13.2021, 1.2021)
  line L3 (-13.2021, -1.2021) -> (-14.4042, 0)
extrude "Extrude19" cut sketch "Follower horizontal bore 45 degree roof (1)" along normal blind 16.2
work_plane "WorkPlane11" AlongDistance 9 ExtraOffset 0
sketch "Upright grip head pocket roof" plane through (9, 0, 0) normal (1, 0, 0) x axis (0, 0, -1)
  line L1 (-182.192, -2.192) -> (-182.192, 2.192)
  line L2 (-184.3841, 0) -> (-182.192, -2.192)
  line L3 (-182.192, 2.192) -> (-184.3841, 0)
extrude "Extrude10" cut sketch "Upright grip head pocket roof" along normal blind 16
work_plane "WorkPlane12" AlongDistance 9 ExtraOffset 0
sketch "Upright grip head pocket roof (1)" plane through (9, 0, 0) normal (1, 0, 0) x axis (0, 0, -1)
  line L1 (-192.192, -2.192) -> (-192.192, 2.192)
  line L2 (-194.3841, 0) -> (-192.192, -2.192)
  line L3 (-192.192, 2.192) -> (-194.3841, 0)
extrude "Extrude11" cut sketch "Upright grip head pocket roof (1)" along normal blind 16
work_plane "WorkPlane1" AlongDistance -4.5 ExtraOffset 0
sketch "Shaft joining M3x8 -15" plane through (0, -4.5, 0) normal (0, 1, 0) x axis (1, 0, 0)
  circle C1 centre (-15, -65) radius 1.5
extrude "Extrude1" new body sketch "Shaft joining M3x8 -15" along normal blind 8 bodies "HARDWARE Shaft joining M3x8 -15"
work_plane "WorkPlane2" AlongDistance 3.5 ExtraOffset 0
sketch "Button head" plane through (0, 3.5, 0) normal (0, 1, 0) x axis (1, 0, 0)
  circle C1 centre (-15, -65) radius 2.75
extrude "Extrude2" add sketch "Button head" along normal blind 3
work_plane "WorkPlane1" AlongDistance -4.5 ExtraOffset 0
sketch "Shaft joining M3x8 15" plane through (0, -4.5, 0) normal (0, 1, 0) x axis (1, 0, 0)
  circle C1 centre (15, -65) radius 1.5
extrude "Extrude1" new body sketch "Shaft joining M3x8 15" along normal blind 8 bodies "HARDWARE Shaft joining M3x8 15"
work_plane "WorkPlane2" AlongDistance 3.5 ExtraOffset 0
sketch "Button head" plane through (0, 3.5, 0) normal (0, 1, 0) x axis (1, 0, 0)
  circle C1 centre (15, -65) radius 2.75
extrude "Extrude2" add sketch "Button head" along normal blind 3
work_plane "WorkPlane1" AlongDistance -6.5 ExtraOffset 0
sketch "Loose flat printable alignment key" plane through (-6.5, 0, 0) normal (1, 0, 0) x axis (0, 0, -1)
  line L1 (-61.1, 1.5) -> (-61.1, -1.5)
  line L2 (-68.9, 1.5) -> (-61.1, 1.5)
  line L3 (-68.9, -1.5) -> (-68.9, 1.5)
  line L4 (-61.1, -1.5) -> (-68.9, -1.5)
extrude "Extrude1" new body sketch "Loose flat printable alignment key" along normal blind 3 bodies "P28 Shaft alignment key -5"
work_plane "WorkPlane1" AlongDistance 3.5 ExtraOffset 0
sketch "Loose flat printable alignment key" plane through (3.5, 0, 0) normal (1, 0, 0) x axis (0, 0, -1)
  line L1 (-61.1, 1.5) -> (-61.1, -1.5)
  line L2 (-68.9, 1.5) -> (-61.1, 1.5)
  line L3 (-68.9, -1.5) -> (-68.9, 1.5)
  line L4 (-61.1, -1.5) -> (-68.9, -1.5)
extrude "Extrude1" new body sketch "Loose flat printable alignment key" along normal blind 3 bodies "P28 Shaft alignment key 5"
work_plane "WorkPlane19" AlongDistance -5 ExtraOffset 0
sketch "Direct cap-head rotor clamp seat" plane through (-5, 0, 0) normal (1, 0, 0) x axis (0, 0, -1)
  line L1 (-60, 22.5) -> (-60, 22)
  line L2 (-70, 22.5) -> (-60, 22.5)
  line L3 (-70, 22) -> (-70, 22.5)
  line L4 (-60, 22) -> (-70, 22)
extrude "Extrude19" add sketch "Direct cap-head rotor clamp seat" along normal blind 10
work_plane "WorkPlane20" AlongDistance 21.9 ExtraOffset 0
sketch "Restore rotor screw through raised seat" plane through (0, 21.9, 0) normal (0, 1, 0) x axis (1, 0, 0)
  circle C1 centre (0, -65) radius 1.7
extrude "Extrude20" cut sketch "Restore rotor screw through raised seat" along normal blind 0.7
work_plane "WorkPlane1" AlongDistance -39.35 ExtraOffset 0
sketch "Main shaft cap M3x8 cap head" plane through (-39.35, 0, 0) normal (1, 0, 0) x axis (0, 0, -1)
  circle C1 centre (-65, 0) radius 1.5
extrude "Extrude1" new body sketch "Main shaft cap M3x8 cap head" along normal blind 8 bodies "HARDWARE Main shaft cap M3x8 cap head"
work_plane "WorkPlane2" AlongDistance -42.35 ExtraOffset 0
sketch "Button head" plane through (-42.35, 0, 0) normal (1, 0, 0) x axis (0, 0, -1)
  circle C1 centre (-65, 0) radius 2.75
extrude "Extrude2" add sketch "Button head" along normal blind 3
work_plane "WorkPlane1" AlongDistance 2 ExtraOffset 0
sketch "Cam M3x10 cap head -45" plane through (2, 0, 0) normal (1, 0, 0) x axis (0, 0, -1)
  circle C1 centre (-39.5442, 25.4558) radius 1.5
extrude "Extrude1" new body sketch "Cam M3x10 cap head -45" along normal blind 10 bodies "HARDWARE Cam M3x10 cap head -45"
work_plane "WorkPlane2" AlongDistance 12 ExtraOffset 0
sketch "Button head" plane through (12, 0, 0) normal (1, 0, 0) x axis (0, 0, -1)
  circle C1 centre (-39.5442, 25.4558) radius 2.75
extrude "Extrude2" add sketch "Button head" along normal blind 3
work_plane "WorkPlane1" AlongDistance 2 ExtraOffset 0
sketch "Cam M3x10 cap head 0" plane through (2, 0, 0) normal (1, 0, 0) x axis (0, 0, -1)
  circle C1 centre (-29, 0) radius 1.5
extrude "Extrude1" new body sketch "Cam M3x10 cap head 0" along normal blind 10 bodies "HARDWARE Cam M3x10 cap head 0"
work_plane "WorkPlane2" AlongDistance 12 ExtraOffset 0
sketch "Button head" plane through (12, 0, 0) normal (1, 0, 0) x axis (0, 0, -1)
  circle C1 centre (-29, 0) radius 2.75
extrude "Extrude2" add sketch "Button head" along normal blind 3
work_plane "WorkPlane1" AlongDistance 2 ExtraOffset 0
sketch "Cam M3x10 cap head 45" plane through (2, 0, 0) normal (1, 0, 0) x axis (0, 0, -1)
  circle C1 centre (-39.5442, -25.4558) radius 1.5
extrude "Extrude1" new body sketch "Cam M3x10 cap head 45" along normal blind 10 bodies "HARDWARE Cam M3x10 cap head 45"
work_plane "WorkPlane2" AlongDistance 12 ExtraOffset 0
sketch "Button head" plane through (12, 0, 0) normal (1, 0, 0) x axis (0, 0, -1)
  circle C1 centre (-39.5442, -25.4558) radius 2.75
extrude "Extrude2" add sketch "Button head" along normal blind 3
work_plane "WorkPlane1" AlongDistance 0 ExtraOffset 0
sketch "Roller axle M3x20 cap head" plane through (0, 0, 0) normal (1, 0, 0) x axis (0, 0, -1)
  circle C1 centre (-12, 0) radius 1.5
extrude "Extrude1" new body sketch "Roller axle M3x20 cap head" along normal blind 20 bodies "HARDWARE Roller axle M3x20 cap head"
work_plane "WorkPlane2" AlongDistance 20 ExtraOffset 0
sketch "Button head" plane through (20, 0, 0) normal (1, 0, 0) x axis (0, 0, -1)
  circle C1 centre (-12, 0) radius 2.75
extrude "Extrude2" add sketch "Button head" along normal blind 3
work_plane "WorkPlane1" AlongDistance -36 ExtraOffset 0
sketch "Crossblock M3x20 cap head (-62, -1)" plane through (-36, 0, 0) normal (1, 0, 0) x axis (0, 0, -1)
  circle C1 centre (-53.5, -62) radius 1.5
extrude "Extrude1" new body sketch "Crossblock M3x20 cap head (-62, -1)" along normal blind 20 bodies "HARDWARE Crossblock M3x20 cap head (-62, -1)"
work_plane "WorkPlane2" AlongDistance -39 ExtraOffset 0
sketch "Button head" plane through (-39, 0, 0) normal (1, 0, 0) x axis (0, 0, -1)
  circle C1 centre (-53.5, -62) radius 2.75
extrude "Extrude2" add sketch "Button head" along normal blind 3
work_plane "WorkPlane1" AlongDistance 16 ExtraOffset 0
sketch "Crossblock M3x20 cap head (-62, 1)" plane through (16, 0, 0) normal (1, 0, 0) x axis (0, 0, -1)
  circle C1 centre (-53.5, -62) radius 1.5
extrude "Extrude1" new body sketch "Crossblock M3x20 cap head (-62, 1)" along normal blind 20 bodies "HARDWARE Crossblock M3x20 cap head (-62, 1)"
work_plane "WorkPlane2" AlongDistance 36 ExtraOffset 0
sketch "Button head" plane through (36, 0, 0) normal (1, 0, 0) x axis (0, 0, -1)
  circle C1 centre (-53.5, -62) radius 2.75
extrude "Extrude2" add sketch "Button head" along normal blind 3
work_plane "WorkPlane1" AlongDistance -36 ExtraOffset 0
sketch "Crossblock M3x20 cap head (-70, -1)" plane through (-36, 0, 0) normal (1, 0, 0) x axis (0, 0, -1)
  circle C1 centre (-53.5, -70) radius 1.5
extrude "Extrude1" new body sketch "Crossblock M3x20 cap head (-70, -1)" along normal blind 20 bodies "HARDWARE Crossblock M3x20 cap head (-70, -1)"
work_plane "WorkPlane2" AlongDistance -39 ExtraOffset 0
sketch "Button head" plane through (-39, 0, 0) normal (1, 0, 0) x axis (0, 0, -1)
  circle C1 centre (-53.5, -70) radius 2.75
extrude "Extrude2" add sketch "Button head" along normal blind 3
work_plane "WorkPlane1" AlongDistance 16 ExtraOffset 0
sketch "Crossblock M3x20 cap head (-70, 1)" plane through (16, 0, 0) normal (1, 0, 0) x axis (0, 0, -1)
  circle C1 centre (-53.5, -70) radius 1.5
extrude "Extrude1" new body sketch "Crossblock M3x20 cap head (-70, 1)" along normal blind 20 bodies "HARDWARE Crossblock M3x20 cap head (-70, 1)"
work_plane "WorkPlane2" AlongDistance 36 ExtraOffset 0
sketch "Button head" plane through (36, 0, 0) normal (1, 0, 0) x axis (0, 0, -1)
  circle C1 centre (-53.5, -70) radius 2.75
extrude "Extrude2" add sketch "Button head" along normal blind 3
work_plane "WorkPlane1" AlongDistance 6.5 ExtraOffset 0
sketch "Rotor clamp M3x16 cap head" plane through (0, 6.5, 0) normal (0, 1, 0) x axis (1, 0, 0)
  circle C1 centre (0, -65) radius 1.5
extrude "Extrude1" new body sketch "Rotor clamp M3x16 cap head" along normal blind 16 bodies "HARDWARE Rotor clamp M3x16 cap head"
work_plane "WorkPlane2" AlongDistance 22.5 ExtraOffset 0
sketch "Button head" plane through (0, 22.5, 0) normal (0, 1, 0) x axis (1, 0, 0)
  circle C1 centre (0, -65) radius 2.75
extrude "Extrude2" add sketch "Button head" along normal blind 3
work_plane "WorkPlane20" AlongDistance 3.9 ExtraOffset 0
sketch "Restore axle bore after adding print feet" plane through (3.9, 0, 0) normal (1, 0, 0) x axis (0, 0, -1)
  circle C1 centre (-12, 0) radius 1.7
extrude "Extrude20" cut sketch "Restore axle bore after adding print feet" along normal blind 16.2
work_plane "WorkPlane21" AlongDistance 3.9 ExtraOffset 0
sketch "Restore nut installation recess after print foot" plane through (3.9, 0, 0) normal (1, 0, 0) x axis (0, 0, -1)
  line L1 (-14.9, 1.6743) -> (-12, 3.3486)
  line L2 (-14.9, -1.6743) -> (-14.9, 1.6743)
  line L3 (-12, -3.3486) -> (-14.9, -1.6743)
  line L4 (-9.1, -1.6743) -> (-12, -3.3486)
  line L5 (-9.1, 1.6743) -> (-9.1, -1.6743)
  line L6 (-12, 3.3486) -> (-9.1, 1.6743)
extrude "Extrude21" cut sketch "Restore nut installation recess after print foot" along normal blind 1.6
work_plane "WorkPlane3" AlongDistance 8 ExtraOffset 0
sketch "Retain one mm preload travel before head meets collar" plane through (8, 0, 0) normal (1, 0, 0) x axis (0, 0, -1)
  line L1 (-56, -51) -> (-56, -59)
  line L2 (-57.1, -51) -> (-56, -51)
  line L3 (-57.1, -59) -> (-57.1, -51)
  line L4 (-56, -59) -> (-57.1, -59)
extrude "Extrude3" cut sketch "Retain one mm preload travel before head meets collar" along normal blind 8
